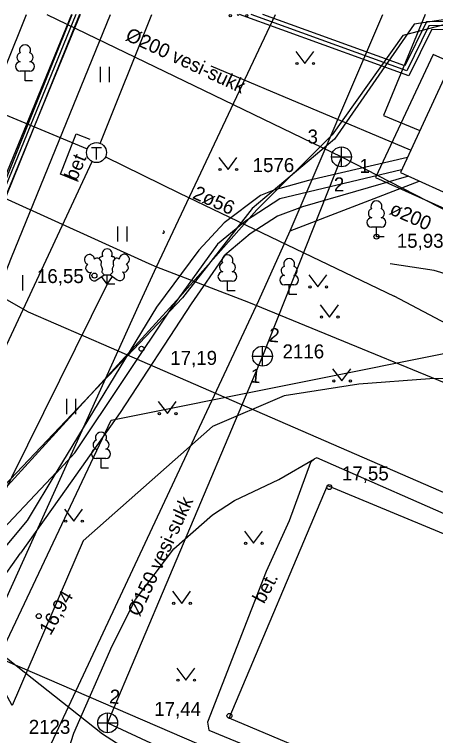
# Model space of a CAD drawing. Extents: x 713497 to 713863, y 6590062 to 6590327.
# Drawn here: x 713529.76 to 713550.85, y 6590291.24 to 6590327.39 of the extents above; entities that cross this region are included whole.
import ezdxf

# ---------------------------------------------------------------- set-up
doc = ezdxf.new("R2010")
doc.units = 0
for name, color, linetype in [('HALJASTUS', 7, 'Continuous'), ('HOONE', 7, 'Continuous'), ('HOONEDET', 7, 'Continuous'), ('KAEVU_NR', 7, 'Continuous'), ('KKAEV', 7, 'Continuous'), ('KORGUS', 7, 'Continuous'), ('KPKAABEL', 7, 'Continuous'), ('KTRASS', 7, 'Continuous'), ('MPKAABEL', 7, 'Continuous'), ('PUU', 7, 'Continuous'), ('RAJATIS', 7, 'Continuous'), ('SIKAEV', 7, 'Continuous'), ('SITRASS', 7, 'Continuous'), ('TEE', 7, 'Continuous'), ('TKAEV', 7, 'Continuous'), ('TORU NR', 7, 'Continuous'), ('TTRASS', 7, 'Continuous'), ('VTRASS', 7, 'Continuous'), ('По умолчанию', 7, 'Continuous'), ('Слой 1', 7, 'Continuous')]:
    doc.layers.add(name, color=color, linetype=linetype)

msp = doc.modelspace()

# ---------------------------------------------------------------- linework, layer by layer
at = {"layer": 'HALJASTUS'}
for p, q in [((713540.924, 6590327.391), (713540.97, 6590327.33)), ((713540.97, 6590327.33), (713541.015, 6590327.391)), ((713543.847, 6590325.537), (713544.31, 6590324.93)), ((713544.31, 6590324.93), (713544.756, 6590325.537)), ((713534.051, 6590324.762), (713534.051, 6590324.001)), ((713534.506, 6590324.762), (713534.506, 6590324.001)), ((713539.997, 6590320.227), (713540.46, 6590319.62)), ((713540.46, 6590319.62), (713540.906, 6590320.227)), ((713534.93, 6590316.763), (713534.93, 6590316.002)), ((713535.385, 6590316.763), (713535.385, 6590316.002)), ((713530.162, 6590314.315), (713530.162, 6590313.554)), ((713544.497, 6590314.337), (713544.96, 6590313.73)), ((713544.96, 6590313.73), (713545.406, 6590314.337)), ((713545.077, 6590312.827), (713545.54, 6590312.22)), ((713545.54, 6590312.22), (713545.986, 6590312.827)), ((713545.697, 6590309.627), (713546.16, 6590309.02)), ((713546.16, 6590309.02), (713546.606, 6590309.627)), ((713532.364, 6590308.119), (713532.364, 6590307.358)), ((713532.819, 6590308.119), (713532.819, 6590307.358)), ((713536.957, 6590307.987), (713537.42, 6590307.38)), ((713537.42, 6590307.38), (713537.866, 6590307.987)), ((713532.267, 6590302.597), (713532.73, 6590301.99)), ((713532.73, 6590301.99), (713533.176, 6590302.597)), ((713541.277, 6590301.487), (713541.74, 6590300.88)), ((713541.74, 6590300.88), (713542.186, 6590301.487)), ((713537.677, 6590298.477), (713538.14, 6590297.87)), ((713538.14, 6590297.87), (713538.586, 6590298.477)), ((713537.887, 6590294.627), (713538.35, 6590294.02)), ((713538.35, 6590294.02), (713538.796, 6590294.627))]:
    msp.add_line(p, q, dxfattribs=at)
msp.add_lwpolyline([(713552.76, 6590313.96), (713550.78, 6590314.56), (713548.58, 6590314.89)], dxfattribs=at)
for centre in [(713540.569, 6590327.33), (713541.398, 6590327.33), (713543.909, 6590324.93), (713544.738, 6590324.93), (713540.059, 6590319.62), (713540.888, 6590319.62), (713544.559, 6590313.73), (713545.388, 6590313.73), (713545.139, 6590312.22), (713545.968, 6590312.22), (713545.759, 6590309.02), (713546.588, 6590309.02), (713537.019, 6590307.38), (713537.848, 6590307.38), (713532.329, 6590301.99), (713533.158, 6590301.99), (713541.339, 6590300.88), (713542.168, 6590300.88), (713537.739, 6590297.87), (713538.568, 6590297.87), (713537.949, 6590294.02), (713538.778, 6590294.02)]:
    msp.add_circle(centre, 0.055, dxfattribs=at)
at = {"layer": 'HOONE'}
for points in [[(713536.87, 6590314.74), (713542.837, 6590327.391)], [(713519.557, 6590322.588), (713519.629, 6590322.555), (713536.489, 6590314.913), (713536.87, 6590314.74), (713541.49, 6590312.96)], [(713536.487, 6590314.908), (713536.87, 6590314.74)], [(713535.98, 6590312.79), (713536.87, 6590314.74)], [(713576.17, 6590314.75), (713587.41, 6590310.13), (713584.84, 6590303.68), (713574.46, 6590277.88), (713561.56, 6590283.23), (713540.52, 6590292.12), (713545.44, 6590303.77), (713562.22, 6590296.81), (713560.95, 6590293.78), (713566.64, 6590291.4), (713576.17, 6590314.75)], [(713527.264, 6590284.61), (713523.87, 6590286.01), (713535.98, 6590312.79)], [(713541.49, 6590312.96), (713555.39, 6590307.25)]]:
    msp.add_lwpolyline(points, dxfattribs=at)
at = {"layer": 'HOONEDET'}
for points in [[(713547.85, 6590319.22), (713555.61, 6590315.72), (713558.45, 6590321.94), (713550.73, 6590325.38), (713547.85, 6590319.22)], [(713552.8, 6590301.69), (713544.9, 6590305.16), (713544.79, 6590305.11), (713544.58, 6590304.93), (713543.52, 6590302.01), (713542.37, 6590299.46), (713539.43, 6590291.91), (713539.49, 6590291.52), (713543.9, 6590289.7), (713547.82, 6590287.88), (713558.4, 6590283.41), (713566.79, 6590279.77), (713574.52, 6590276.62), (713574.85, 6590277.01), (713576.84, 6590281.98), (713578.43, 6590285.96)]]:
    msp.add_lwpolyline(points, dxfattribs=at)
at = {"layer": 'KKAEV'}
for p, q in [((713546.138, 6590319.75), (713546.138, 6590320.75)), ((713545.638, 6590320.25), (713546.638, 6590320.25)), ((713542.182, 6590309.761), (713542.182, 6590310.761)), ((713541.682, 6590310.261), (713542.682, 6590310.261)), ((713534.43, 6590291.38), (713534.43, 6590292.38)), ((713533.93, 6590291.88), (713534.93, 6590291.88))]:
    msp.add_line(p, q, dxfattribs=at)
for centre in [(713546.138, 6590320.25), (713542.182, 6590310.261), (713534.43, 6590291.88)]:
    msp.add_circle(centre, 0.5, dxfattribs=at)
at = {"layer": 'KORGUS'}
for centre in [(713547.89, 6590316.25), (713533.77, 6590314.3), (713536.13, 6590310.63), (713545.53, 6590303.7), (713530.98, 6590297.23), (713540.53, 6590292.23)]:
    msp.add_circle(centre, 0.125, dxfattribs=at)
at = {"layer": 'KPKAABEL'}
for points in [[(713550.333, 6590327.391), (713548.25, 6590322.33), (713550.06, 6590321.57)], [(713543.57, 6590316.55), (713550.03, 6590319.04)], [(713542, 6590313.05), (713543.57, 6590316.55)], [(713530.003, 6590287.396), (713542, 6590313.05)]]:
    msp.add_lwpolyline(points, dxfattribs=at)
at = {"layer": 'KTRASS'}
for points in [[(713531.384, 6590327.391), (713546.138, 6590320.25)], [(713546.138, 6590320.25), (713542.182, 6590310.261)], [(713546.138, 6590320.25), (713566.294, 6590309.901)], [(713542.182, 6590310.261), (713534.43, 6590291.88)], [(713534.43, 6590291.88), (713547.405, 6590285.835)]]:
    msp.add_lwpolyline(points, dxfattribs=at)
at = {"layer": 'MPKAABEL'}
for points in [[(713556.424, 6590327.391), (713556.223, 6590326.664), (713552.132, 6590327.245), (713549.78, 6590326.91), (713545.79, 6590321.14), (713541.662, 6590317.664), (713538.182, 6590313.186), (713528.61, 6590303.11), (713525.635, 6590299.613), (713521.549, 6590293.725), (713518.804, 6590288.58), (713514.43, 6590279.53), (713512.558, 6590274.575), (713509.964, 6590266.002), (713509.002, 6590264.701), (713505.064, 6590265.776), (713496.861, 6590269.111)], [(713533.052, 6590327.391), (713528.05, 6590315.2), (713512.628, 6590321.645), (713503.54, 6590325.85), (713500.04, 6590327.391)], [(713532.838, 6590327.391), (713527.94, 6590315.46), (713512.709, 6590321.828), (713503.624, 6590326.03), (713500.535, 6590327.391)], [(713532.621, 6590327.391), (713527.83, 6590315.73), (713512.79, 6590322.011), (713503.705, 6590326.213), (713501.031, 6590327.391)], [(713557.307, 6590327.391), (713556.644, 6590326.552), (713552.106, 6590327.081), (713549.22, 6590326.34), (713545.68, 6590321.35), (713541.902, 6590317.59), (713538.038, 6590313.239), (713528.706, 6590303.01), (713525.957, 6590299.38), (713525.726, 6590297.521), (713529.032, 6590295.391), (713534.179, 6590291.338), (713537.678, 6590289.076)], [(713557.538, 6590327.391), (713555.99, 6590325.703), (713552.11, 6590326.65), (713550.646, 6590326.622), (713549.51, 6590324.309), (713541.04, 6590327.391)], [(713557.264, 6590327.391), (713555.92, 6590325.93), (713552.13, 6590326.85), (713550.52, 6590326.82), (713549.41, 6590324.558), (713541.622, 6590327.391)], [(713556.997, 6590327.391), (713555.86, 6590326.15), (713552.15, 6590327.05), (713550.394, 6590327.018), (713549.31, 6590324.807), (713542.207, 6590327.391)], [(713543.57, 6590316.55), (713548.203, 6590327.391)], [(713549.6, 6590320.58), (713539.617, 6590324.797)], [(713549.44, 6590320.22), (713544.49, 6590319.07), (713542.76, 6590318.58), (713542.09, 6590318.31), (713540.27, 6590316.94), (713538.99, 6590315.57), (713536.87, 6590312.72)], [(713549.15, 6590319.6), (713543.06, 6590318.15), (713541.33, 6590317.03), (713539.93, 6590315.88), (713537.72, 6590312.81)], [(713549.5, 6590319.28), (713544.19, 6590317.74), (713542.93, 6590317.28), (713541.56, 6590316.4), (713540.29, 6590315.33), (713538.61, 6590312.88)], [(713538.61, 6590312.88), (713535.05, 6590307.43), (713532.36, 6590303.61), (713530.064, 6590300.386)], [(713531.844, 6590304.388), (713532.79, 6590305.42), (713537.72, 6590312.81)], [(713536.87, 6590312.72), (713531.89, 6590304.492)], [(713515.66, 6590285.591), (713524.88, 6590297.03), (713531.868, 6590304.442)], [(713531.89, 6590304.492), (713530.4, 6590302.03), (713519.06, 6590288.44), (713516.291, 6590285.326)], [(713517.352, 6590284.879), (713522.33, 6590291.1), (713523.74, 6590292.58), (713528.97, 6590298.85), (713530.064, 6590300.386)]]:
    msp.add_lwpolyline(points, dxfattribs=at)
at = {"layer": 'PUU'}
for p, q in [((713530.532, 6590324.545), (713530.052, 6590324.545)), ((713530.292, 6590324.07), (713530.292, 6590324.545)), ((713530.672, 6590324.07), (713530.292, 6590324.07)), ((713548.13, 6590316.725), (713547.65, 6590316.725)), ((713547.89, 6590316.25), (713547.89, 6590316.725)), ((713548.27, 6590316.25), (713547.89, 6590316.25)), ((713533.894, 6590314.082), (713534.254, 6590314.337)), ((713534.404, 6590313.862), (713534.129, 6590314.247)), ((713534.254, 6590314.337), (713534.549, 6590314.337)), ((713534.404, 6590313.862), (713534.404, 6590314.337)), ((713534.404, 6590313.862), (713534.674, 6590314.252)), ((713534.549, 6590314.337), (713534.909, 6590314.092)), ((713534.784, 6590313.862), (713534.404, 6590313.862)), ((713540.67, 6590314.015), (713540.19, 6590314.015)), ((713540.43, 6590313.54), (713540.43, 6590314.015)), ((713543.76, 6590313.835), (713543.28, 6590313.835)), ((713543.52, 6590313.36), (713543.52, 6590313.835)), ((713540.81, 6590313.54), (713540.43, 6590313.54)), ((713543.9, 6590313.36), (713543.52, 6590313.36)), ((713534.34, 6590305.125), (713533.86, 6590305.125)), ((713534.1, 6590304.65), (713534.1, 6590305.125)), ((713534.48, 6590304.65), (713534.1, 6590304.65))]:
    msp.add_line(p, q, dxfattribs=at)
for points in [[(713533.991, 6590315.149), (713534.094, 6590315.047), (713534.109, 6590315.017), (713534.109, 6590314.962), (713534.094, 6590314.872), (713534.094, 6590314.827), (713534.114, 6590314.747), (713534.154, 6590314.657), (713534.164, 6590314.612), (713534.159, 6590314.567), (713534.144, 6590314.502), (713534.144, 6590314.472), (713534.164, 6590314.432), (713534.189, 6590314.402), (713534.254, 6590314.337)], [(713534.808, 6590315.163), (713534.714, 6590315.047), (713534.699, 6590315.017), (713534.699, 6590314.962), (713534.714, 6590314.872), (713534.719, 6590314.827), (713534.699, 6590314.747), (713534.659, 6590314.657), (713534.649, 6590314.612), (713534.654, 6590314.567), (713534.669, 6590314.502), (713534.669, 6590314.472), (713534.649, 6590314.432), (713534.624, 6590314.402), (713534.554, 6590314.337)], [(713534.404, 6590313.862), (713527.207, 6590299.343)]]:
    msp.add_lwpolyline(points, dxfattribs=at)
for centre, radius, start, end in [((713530.292, 6590325.59), 0.277, 332.5799, 207.4201), ((713530.122, 6590325.243), 0.233, 109.0217, 253.1415), ((713530.462, 6590325.243), 0.233, 286.8508, 70.9859), ((713530.055, 6590324.783), 0.238, 90.0016, 269.3953), ((713530.53, 6590324.783), 0.238, 270.6047, 89.9984), ((713547.89, 6590317.77), 0.277, 332.5799, 207.4201), ((713547.72, 6590317.423), 0.233, 109.0217, 253.1415), ((713548.06, 6590317.423), 0.233, 286.8508, 70.9859), ((713547.653, 6590316.962), 0.238, 90.0016, 269.3953), ((713548.127, 6590316.962), 0.238, 270.6047, 89.9984), ((713534.404, 6590315.382), 0.256, 90.0013, 211.0159), ((713534.404, 6590315.382), 0.256, 328.9841, 89.9987), ((713533.52, 6590315.099), 0.256, 125.5389, 246.5536), ((713533.52, 6590315.099), 0.256, 4.5218, 125.5364), ((713535.264, 6590315.115), 0.256, 55.522, 176.5367), ((713535.264, 6590315.115), 0.256, 294.5049, 55.5195), ((713540.43, 6590315.06), 0.277, 332.5799, 207.4201), ((713533.907, 6590314.966), 0.202, 65.2382, 130.7412), ((713534.166, 6590315.049), 0.202, 84.7965, 150.2995), ((713534.641, 6590315.049), 0.202, 34.3857, 95.2035), ((713534.88, 6590314.975), 0.202, 50.3173, 111.1351), ((713540.26, 6590314.713), 0.233, 109.0217, 253.1415), ((713540.6, 6590314.713), 0.233, 286.8508, 70.9859), ((713543.52, 6590314.88), 0.277, 332.5799, 207.4201), ((713533.549, 6590314.682), 0.224, 125.4667, 288.5349), ((713535.244, 6590314.697), 0.224, 252.5235, 55.5918), ((713543.35, 6590314.533), 0.233, 109.0217, 253.1415), ((713543.69, 6590314.533), 0.233, 286.8508, 70.9859), ((713533.758, 6590314.276), 0.237, 125.5377, 305.5366), ((713535.042, 6590314.288), 0.237, 235.5219, 55.5208), ((713540.193, 6590314.252), 0.238, 90.0016, 269.3953), ((713540.667, 6590314.252), 0.238, 270.6047, 89.9984), ((713543.283, 6590314.072), 0.238, 90.0016, 269.3953), ((713543.757, 6590314.072), 0.238, 270.6047, 89.9984), ((713534.1, 6590306.17), 0.277, 332.5799, 207.4201), ((713533.93, 6590305.823), 0.233, 109.0217, 253.1415), ((713534.27, 6590305.823), 0.233, 286.8508, 70.9859), ((713533.863, 6590305.362), 0.238, 90.0016, 269.3953), ((713534.337, 6590305.362), 0.238, 270.6047, 89.9984)]:
    msp.add_arc(centre, radius, start, end, dxfattribs=at)
at = {"layer": 'RAJATIS'}
msp.add_lwpolyline([(713549.09, 6590319.47), (713555.14, 6590316.73), (713557.28, 6590321.39), (713551.26, 6590324.16), (713549.09, 6590319.47)], dxfattribs=at)
at = {"layer": 'SITRASS'}
for points in [[(713564.43, 6590297.7), (713552.93, 6590302.7), (713534.618, 6590310.666), (713530.47, 6590312.47), (713526.3, 6590314.84), (713512, 6590321.218), (713498.159, 6590327.391)], [(713496.861, 6590307.708), (713502.281, 6590305.611), (713510.011, 6590302.954), (713510.942, 6590302.591), (713521.663, 6590298.107), (713527.894, 6590295.506), (713527.931, 6590295.59), (713554.1, 6590284.28), (713575.48, 6590274.78)]]:
    msp.add_lwpolyline(points, dxfattribs=at)
at = {"layer": 'TEE'}
for points in [[(713517.818, 6590295.479), (713526.169, 6590316.979), (713530.364, 6590327.391)], [(713533.017, 6590327.391), (713528.335, 6590315.808), (713519.593, 6590294.779)], [(713573.49, 6590310.58), (713571.43, 6590310.51), (713568.73, 6590310.13), (713566.75, 6590309.6), (713565.2, 6590309.33), (713563.34, 6590309.28), (713559.47, 6590309.2), (713550.571, 6590309.122), (713547.007, 6590308.859), (713543.266, 6590308.267), (713539.684, 6590306.737), (713533.203, 6590301.01), (713529.652, 6590292.758), (713524.443, 6590302.359), (713528.272, 6590311.829), (713529.607, 6590315.209), (713534.577, 6590327.391)], [(713532.968, 6590319.022), (713532.076, 6590319.389), (713532.858, 6590321.41), (713533.545, 6590321.138)], [(713532.071, 6590289.283), (713532.73, 6590291.37), (713534.66, 6590295.74), (713535.82, 6590298.06), (713537.75, 6590300.6), (713539.68, 6590302.31), (713540.79, 6590303.03), (713543, 6590304.08), (713544.79, 6590305.11)]]:
    msp.add_lwpolyline(points, dxfattribs=at)
at = {"layer": 'TKAEV'}
for p, q in [((713533.621, 6590320.715), (713534.121, 6590320.715)), ((713533.871, 6590320.115), (713533.871, 6590320.715))]:
    msp.add_line(p, q, dxfattribs=at)
msp.add_circle((713533.871, 6590320.465), 0.5, dxfattribs=at)
at = {"layer": 'TTRASS'}
for points in [[(713517.262, 6590327.391), (713533.409, 6590320.658)], [(713534.057, 6590320.929), (713536.648, 6590327.391)], [(713519.7, 6590297.85), (713520.77, 6590300.06), (713523.73, 6590298.74), (713533.659, 6590320.012)], [(713534.32, 6590320.245), (713538.036, 6590318.423), (713548.77, 6590313.26)], [(713567.76, 6590294.15), (713565.34, 6590295.05), (713566.82, 6590298.45), (713557.41, 6590302.34), (713559.67, 6590307.5), (713548.77, 6590313.26)]]:
    msp.add_lwpolyline(points, dxfattribs=at)
at = {"layer": 'VTRASS'}
msp.add_lwpolyline([(713523.675, 6590305.027), (713532.649, 6590327.391)], dxfattribs=at)
at = {"layer": 'По умолчанию'}
msp.add_arc((713537.218, 6590316.48), 0.055, 207.2719, 105.164, dxfattribs=at)
at = {"layer": 'Слой 1'}
msp.add_lwpolyline([(713534.6, 6590307.05), (713570.51, 6590314.26), (713572.89, 6590321.37), (713595.83, 6590312.09), (713577.56, 6590268.53), (713526.91, 6590290.79)], close=True, dxfattribs=at)

# ---------------------------------------------------------------- texts
at = {"layer": 'HOONEDET'}
msp.add_text('bet', height=0.7, rotation=67.3344, dxfattribs=at).set_placement((713532.877, 6590319.009))
at = {"layer": 'KAEVU_NR'}
for s, p in [('2116', (713543.19, 6590310.15)), ('2123', (713530.48, 6590291.33))]:
    msp.add_text(s, height=0.7, dxfattribs=at).set_placement(p)
at = {"layer": 'KORGUS'}
for s, p in [('15,93', (713548.91, 6590315.695)), ('16,55', (713530.89, 6590313.925)), ('17,19', (713537.566, 6590309.825)), ('17,55', (713546.163, 6590304.035)), ('17,44', (713536.763, 6590292.225))]:
    msp.add_text(s, height=0.7, dxfattribs=at).set_placement(p)
msp.add_text('16,94', height=0.7, rotation=59.8811, dxfattribs=at).set_placement((713531.563, 6590296.225))
at = {"layer": 'KTRASS'}
for s, rotation, p in [('%%c200 vesi-sukk', 335.1714, (713535.268, 6590326.125)), ('%%c150 vesi-sukk', 65.1584, (713536.023, 6590297.166))]:
    msp.add_text(s, height=0.7, rotation=rotation, dxfattribs=at).set_placement(p)
at = {"layer": 'SIKAEV'}
msp.add_text('1576', height=0.7, dxfattribs=at).set_placement((713541.69, 6590319.49))
at = {"layer": 'TEE'}
msp.add_text('bet.', height=0.7, rotation=61.6992, dxfattribs=at).set_placement((713542.256, 6590297.811))
at = {"layer": 'TORU NR'}
for s, p in [('3', (713544.44, 6590320.92)), ('1', (713547.04, 6590319.45)), ('2', (713545.76, 6590318.52))]:
    msp.add_text(s, height=0.7, dxfattribs=at).set_placement(p)
for s, rotation, p in [('2ø56', 335.9849, (713538.641, 6590318.193)), ('ø200', 336.2153, (713548.49, 6590317.403)), ('2', 354.7103, (713542.481, 6590310.99)), ('1', 354.7103, (713541.551, 6590308.95)), ('2', 354.7103, (713534.491, 6590292.87))]:
    msp.add_text(s, height=0.7, rotation=rotation, dxfattribs=at).set_placement(p)

doc.saveas('drawing.dxf')
